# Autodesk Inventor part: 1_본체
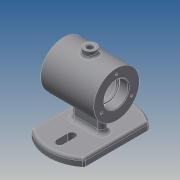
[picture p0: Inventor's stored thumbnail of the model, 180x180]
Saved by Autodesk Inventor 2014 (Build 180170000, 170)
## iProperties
Created: 2017-12
Part Number: 1_본체
Material: Generic
Document SubType Name: Modeling
Designer: kb542-24
Density: 1 g/cm^3
Appearance: Default
Author: kb542-24
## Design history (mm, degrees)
sketch "스케치1"
  geometry: L1 (-35, 0)-(35, 0); L2 (-20, 14)-(-23, 14); L3 (-23, 14)-(-23, 16); L4 (-23, 16)-(-35, 16); L5 (-35, 16)-(-35, 30); L6 (-35, 30)-(35, 30); L7 (35, 30)-(35, 16); L8 (35, 16)-(23, 16); L9 (23, 16)-(23, 14); L10 (23, 14)-(20, 14); L11 (20, 14)-(20, 25); L12 (20, 25)-(-20, 25); L13 (-20, 25)-(-20, 14); 2 further points
  constraints: 26 end point, 8 parallel, 2 horizontal, 2 vertical alignment, 1 coincident, 1 collinear, 1 midpoint, 1 perpendicular, 1 vertical
  dimensions: "d0" = 70 distance of L5.end L6.end; "d1" = 32 diameter of L4 L1; "d2" = 32 diameter of L8 L1; "d3" = 12 distance of L3.end L4.end; "d4" = 12 distance of L7.end L8.end; "d5" = 40 distance of L11.end L12.end; "d6" = 50 diameter of L12 L1; "d7" = 3 distance of L9.end L10.end; "d8" = 28 diameter of L2 L1; "d9" = 28 diameter of L10 L1; "d10" = 60 diameter of L6 L1
revolve "회전1" sketch "스케치1" stored, may be unused: angle "d11" = 90 deg
node "작업 평면1"
sketch "스케치2"
  geometry: L1 (-35, 42.426)-(35, 42.426); L2 (35, 42.426)-(35, -42.426); L3 (-35, 42.426)-(-35, -42.426); L4 (-35, -42.426)-(35, -42.426); A1 r 55 centre (0, 0) between (-35, -42.426) and (35, -42.426); A2 r 55 centre (0, 0) between (35, 42.426) and (-35, 42.426); 1 further point
  constraints: 8 end point, 4 point on circle, 2 centre point, 2 perpendicular, 1 coincident, 1 horizontal, 1 parallel
  dimensions: "d14" = 70 distance of L1.start L1.end; "d15" = 110 diameter of A1; "d17" = 110 diameter of A2
extrude "돌출1" join sketch "스케치2" distance "d18" = 10; taper "d19" = 0 deg
sketch "스케치3"
  geometry: L1 (-35, 42.426)-(-35, -42.426) reference; L2 (35, -42.426)-(35, 42.426) reference; L3 (0, 40)-(0, 24); L4 (5, 40)-(5, 24); L5 (-5, 24)-(-5, 40); L6 (-35, 0)-(35, 0); L7 (0, -40)-(0, -24); L8 (5, -40)-(5, -24); L9 (-5, -24)-(-5, -40); A1 r 55 centre (0, 0) between (-35, -42.426) and (35, -42.426) reference; A2 r 5 centre (0, 40) between (5, 40) and (-5, 40); A3 r 5 centre (0, 24) between (-5, 24) and (5, 24); A4 r 5 centre (0, -40) between (-5, -40) and (5, -40); A5 r 5 centre (0, -24) between (5, -24) and (-5, -24); 2 further points
  constraints: 18 end point, 8 point on circle, 7 symmetric about line, 4 centre point, 4 tangent, 3 midpoint, 2 parallel, 1 vertical alignment, 2 other
  dimensions: "d20" = 5 radius of A2; "d21" = 24 distance of L3.end A1.centre; "d22" = 16 distance of L3.end L3.start
extrude "돌출2" cut sketch "스케치3" distance "d23" = 10; taper "d24" = 0 deg
sketch "스케치4"
  geometry: L1 (35, -42.426)-(35, 42.426) reference; L2 (15, 0)-(-15, 0); L3 (15, -5)-(-15, -5); L4 (-15, 5)-(15, 5); A1 r 55 centre (0, 0) between (35, 42.426) and (-35, 42.426) reference; A2 r 5 centre (15, 0) between (15, -5) and (15, 5); A3 r 5 centre (-15, 0) between (-15, 5) and (-15, -5)
  constraints: 8 end point, 4 point on circle, 4 tangent, 2 centre point, 1 midpoint, 1 parallel, 1 perpendicular
  dimensions: "d25" = 5 radius of A3; "d26" = 30 distance of L2.start L2.end
extrude "돌출3" join sketch "스케치4" stored distance "d27" = 10; taper "d28" = 0 deg
fillet "모깎기1" dims "d29" = 5
sketch "스케치5"
  geometry: C1 r 16 at (0, 0) reference; 1 further point
  constraints: 1 horizontal alignment
  dimensions: "d30" = 23 distance of C1.centre point (-23, 0)
hole "구멍1" sketch "스케치5" at (-23, 0) diameter "d31" = 3.242; stored, may be unused: countersink angle "d35" = 90 deg, drill point angle "d37" = 118 deg; dims "d32" = 8, "d33" = 4, "d34" = 2, "d36" = 10
node "작업 평면2"
sketch "스케치7"
  geometry: L1 (-35, -30)-(-35, 30) reference; C1 r 8 at (0, 0); 1 further point
  constraints: 1 centre point, 1 coincident
  dimensions: "d42" = 35 distance from line of C1.centre L1; "d43" = 16 diameter of C1
extrude "돌출4" join sketch "스케치7" stored distance "d44" = 10; taper "d45" = 0 deg
sketch "스케치8"
  geometry: C1 r 8 at (0, 0) reference; C2 r 4 at (0, 0)
  constraints: 1 centre point, 1 coincident
  dimensions: "d46" = 8 diameter of C2
extrude "돌출5" cut sketch "스케치8" stored distance "d47" = 10; taper "d48" = 0 deg
node "작업 평면3"
sketch "스케치9"
  geometry: L1 (-35, 30)-(-35, -30) reference; L2 (35, 30)-(-35, 30) reference; 2 further points
  constraints: 1 other
  dimensions: "d49" = 35 distance from line of point (0, 0) L1; "d50" = 30 distance from line of point (0, 0) L2
feature "엠보싱1" sketch "스케치9" dims "d0" = 70, "d1" = 32, "d2" = 32, "d3" = 12, "d4" = 12, "d5" = 40, "d6" = 50, "d7" = 3, "d8" = 28, "d9" = 28, "d10" = 60, "d14" = 70, "d15" = 110, "d17" = 110, "d51" = 0.5, "d52" = 0
fillet "모깎기2" dims "d53" = 0.3
fillet "모깎기3" dims "d54" = 3
chamfer "모따기1" distance "d55" = 1; stored, may be unused: second distance "d56" = 2, angle "d57" = 45 deg
chamfer "모따기2" distance "d58" = 1; stored, may be unused: second distance "d59" = 2, angle "d60" = 45 deg
fillet "모깎기4" dims "d61" = 3
fillet "모깎기5" dims "d62" = 3
fillet "모깎기6" dims "d63" = 3
node "솔리드1"
pattern_circular "원형 패턴1" dims angle "d39" = 360 deg
mirror "대칭1"
other parameters: "d12" = -62, "d41" = 37
